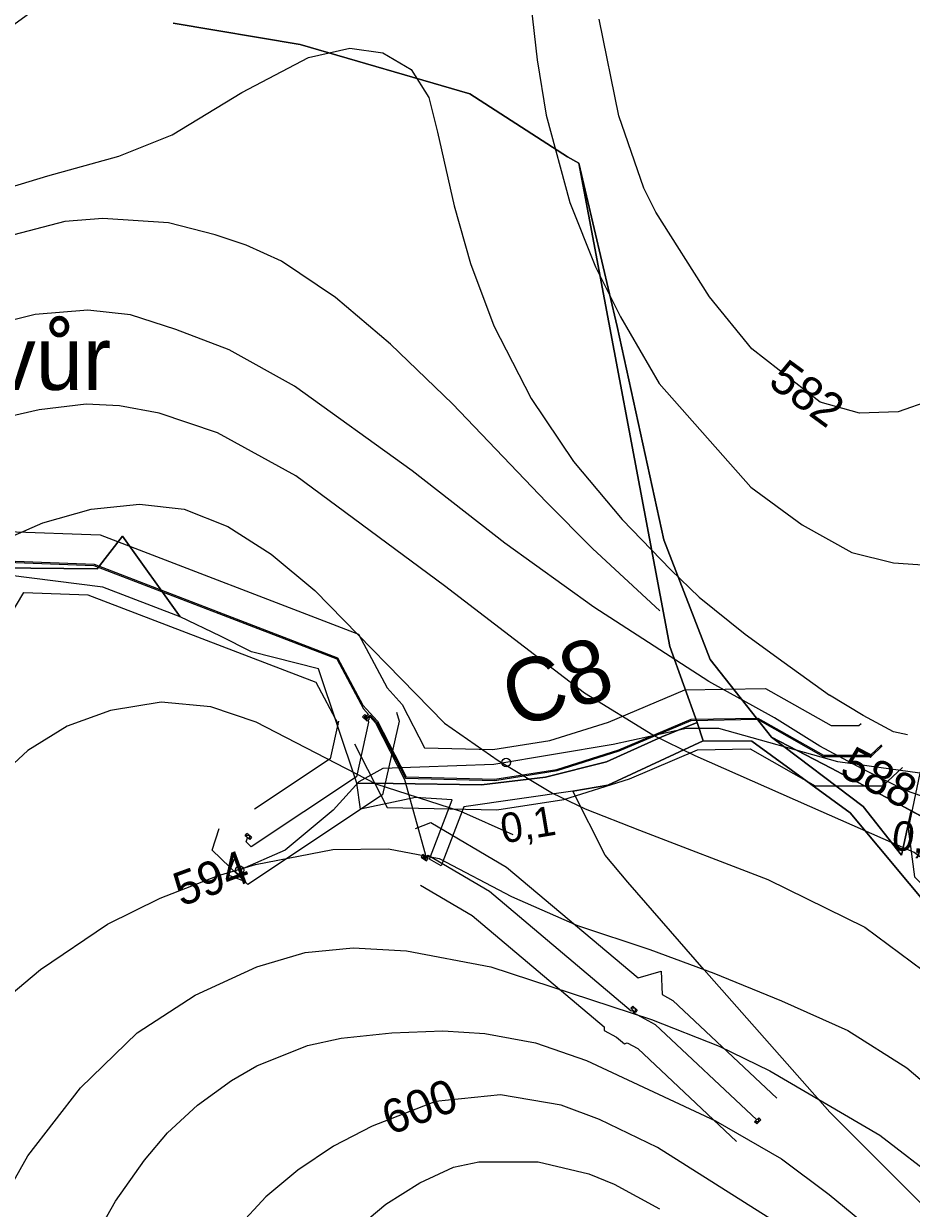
# Model space of a CAD drawing. Extents: x -709418 to -703832, y -1161719 to -1157826.
# Drawn here: x -705715.8 to -705505.5, y -1159483.1 to -1159202.3 of the extents above; entities that cross this region are included whole.
import ezdxf

# ---------------------------------------------------------------- set-up
doc = ezdxf.new("R2010")
doc.units = 0
for name, color, linetype in [('102_obvod PÚ', 7, 'Continuous'), ('103_hranice KÚ', 7, 'Continuous'), ('105_místní názvy', 7, 'Continuous'), ('110_silnice II. třídy a III. třídy', 7, 'Continuous'), ('120_vrstevnice hlavní', 7, 'Continuous'), ('121_vrstevnice hlavní_popis', 7, 'Continuous'), ('122_vrstevnice základní', 7, 'Continuous'), ('124_vrstevnice doplňková', 7, 'Continuous'), ('201_orná půda_KN', 7, 'Continuous'), ('206_TTP_KN', 7, 'Continuous'), ('210_ostatní plocha_KN', 7, 'Continuous'), ('301_polní cesta_stav', 7, 'Continuous'), ('302_polní cesta_stav_popis', 7, 'Continuous'), ('311_polní cesta_staničení', 7, 'Continuous'), ('708_el NN nadzemní a podzemní_ E.ON', 7, 'Continuous'), ('735_OP sítí TI', 7, 'Continuous'), ('Trasa-Hlavni  staniceni', 7, 'Continuous')]:
    doc.layers.add(name, color=color, linetype=linetype)

# ---------------------------------------------------------------- blocks, each defined once
blk = doc.blocks.new('Elektro - Implicitní$0$NN6301')
for points in [[(0, -0.7), (-0.7, 0)], [(-0.7, -0.7), (-0.7, 0), (0.7, 0), (0.7, -0.7)], [(-0.7, -0.7), (0.7, -0.7)], [(0, -0.7), (0.7, 0)]]:
    blk.add_lwpolyline(points)
blk = doc.blocks.new('Elektro - Implicitní$0$NN6201')
for points in [[(0.75, 0), (-0.75, 0)], [(-0.75, 0), (-0.75, -0.75)], [(0.75, -0.75), (0.75, 0)], [(-0.75, -0.75), (0.75, -0.75)], [(0.37, -0.18), (-0.38, -0.18)], [(-0.38, -0.18), (-0.38, -0.56)], [(-0.38, -0.56), (0.37, -0.56)], [(0.32, -0.23), (-0.33, -0.23)], [(-0.33, -0.23), (-0.33, -0.51)], [(-0.33, -0.51), (0.32, -0.51)], [(0.27, -0.27), (-0.28, -0.27)], [(-0.28, -0.27), (-0.28, -0.46)], [(-0.28, -0.46), (0.27, -0.46)], [(0.23, -0.32), (-0.23, -0.32)], [(-0.23, -0.32), (-0.23, -0.42)], [(-0.23, -0.42), (0.23, -0.42)], [(-0.19, -0.37), (0.19, -0.37)], [(0.23, -0.42), (0.23, -0.32)], [(0.27, -0.46), (0.27, -0.27)], [(0.32, -0.51), (0.32, -0.23)], [(0.37, -0.56), (0.37, -0.18)]]:
    blk.add_lwpolyline(points)
blk = doc.blocks.new('_kolecko-HB')
blk.add_circle((0, 0), 0.5)

msp = doc.modelspace()

# ---------------------------------------------------------------- linework, layer by layer
at = {"layer": '102_obvod PÚ'}
for points in [[(-705680.34, -1159202.12), (-705650.29, -1159207.21), (-705610.07, -1159218.91), (-705586.94, -1159233.79), (-705584.26, -1159235.35), (-705575.14, -1159274.02), (-705564.11, -1159324.58), (-705553.14, -1159353), (-705538.64, -1159371.35), (-705524.52, -1159378.74), (-705509.01, -1159386.99), (-705500.95, -1159391.28), (-705503.33, -1159398.39), (-705497.56, -1159411.85), (-705490.04, -1159416.53), (-705487.81, -1159418.64), (-705455.58, -1159447.44), (-705449.77, -1159447.44), (-705446.39, -1159448.44), (-705437.72, -1159450.61), (-705427.05, -1159453.12), (-705405.69, -1159458.61), (-705388.63, -1159462.82)], [(-705499.42, -1159485.62), (-705524.82, -1159460.29), (-705554.6, -1159426.55), (-705572.65, -1159405.79), (-705577.99, -1159399.35), (-705585.69, -1159384.22), (-705611.52, -1159387.9), (-705616.84, -1159401.92), (-705619.66, -1159400.28), (-705614.27, -1159386.22), (-705622.94, -1159385.65), (-705636, -1159388.43), (-705636.84, -1159382.26), (-705645.9, -1159355.21), (-705661.81, -1159351.18), (-705669.12, -1159347.43), (-705678.73, -1159342.87), (-705697, -1159335.87), (-705719.47, -1159333.02)]]:
    msp.add_lwpolyline(points, dxfattribs=at)
at = {"layer": '103_hranice KÚ'}
msp.add_lwpolyline([(-705225.01, -1159488.33), (-705244.62, -1159481.43), (-705265.81, -1159464.97), (-705344.08, -1159443.34), (-705385, -1159423.78), (-705409.33, -1159422.89), (-705434.44, -1159402.64), (-705455.51, -1159396.18), (-705483.68, -1159375.34), (-705500.95, -1159391.28), (-705509.01, -1159386.99), (-705524.52, -1159378.74), (-705538.64, -1159371.35), (-705553.14, -1159353), (-705564.11, -1159324.58), (-705575.14, -1159274.02), (-705584.26, -1159235.35), (-705586.94, -1159233.79), (-705610.07, -1159218.91), (-705650.29, -1159207.21), (-705680.34, -1159202.12)], dxfattribs=at)
at = {"layer": '110_silnice II. třídy a III. třídy'}
msp.add_lwpolyline([(-705425.72, -1159251.12), (-705459.29, -1159299.78), (-705480.06, -1159330.8), (-705495.83, -1159360.32), (-705503.49, -1159379.89), (-705506.27, -1159393.13), (-705504.73, -1159404.52), (-705453.28, -1159456.24), (-705424.63, -1159492.88), (-705411.38, -1159516.59), (-705404.7, -1159537.44), (-705401.75, -1159556.15), (-705377.61, -1159618.68), (-705336.72, -1159700.9), (-705321.44, -1159727.98), (-705286.96, -1159784.24)], dxfattribs=at)
at = {"layer": '120_vrstevnice hlavní'}
for points in [[(-705381.94, -1159487.18), (-705402.79, -1159477.04), (-705418.64, -1159469.88), (-705430.98, -1159461.82), (-705443.17, -1159452.24), (-705458.78, -1159437.51), (-705473.54, -1159423.6), (-705487.44, -1159411.53), (-705504.82, -1159398.74), (-705529.51, -1159387.8), (-705556.73, -1159375.81), (-705566.74, -1159370.95), (-705582.9, -1159360.93), (-705616.08, -1159335.48), (-705651.3, -1159309.45), (-705669.87, -1159299.28), (-705683.68, -1159294.6), (-705693.07, -1159292.84), (-705700.93, -1159292.46), (-705712.13, -1159293.77), (-705722.22, -1159296.11)], [(-705538.14, -1159486.07), (-705565.6, -1159468.62), (-705579.33, -1159462.05), (-705588.48, -1159458.61), (-705602.78, -1159456.18), (-705618.23, -1159457.75), (-705633.24, -1159463.62), (-705642.4, -1159468.34), (-705650.83, -1159474.06), (-705658.41, -1159480.35), (-705665.14, -1159487.64)]]:
    msp.add_lwpolyline(points, dxfattribs=at)
at = {"layer": '122_vrstevnice základní'}
for points in [[(-705719.49, -1159203.45), (-705705.95, -1159193.52), (-705691, -1159179.4), (-705675.18, -1159163.74), (-705664.19, -1159155.41), (-705651.93, -1159148.4), (-705644.22, -1159146.22), (-705636.86, -1159144.54), (-705629.16, -1159144.58), (-705621.63, -1159145.13), (-705613.95, -1159147.56), (-705607.81, -1159152.22), (-705602.38, -1159162.17), (-705599.36, -1159173.47), (-705595.59, -1159197.61), (-705594.12, -1159210.8), (-705591.96, -1159223.98), (-705586.39, -1159244.68), (-705580.31, -1159259.94), (-705574.38, -1159271.78), (-705565.22, -1159287.56), (-705543.49, -1159312.11), (-705531.39, -1159321.07), (-705519.61, -1159327.63)], [(-705443.75, -1159201.76), (-705457.62, -1159240.37), (-705466.63, -1159260.97), (-705477.36, -1159276.41), (-705484.94, -1159282.85), (-705496.38, -1159289.57), (-705500.96, -1159291.57), (-705508.63, -1159294.3), (-705517.78, -1159294.59), (-705527.05, -1159292), (-705543.31, -1159279.34), (-705553.3, -1159266.98), (-705566.03, -1159246.95), (-705568.89, -1159241.23), (-705574.75, -1159224.07), (-705579.47, -1159201.19)], [(-705727.83, -1159243.74), (-705710.02, -1159238.35), (-705693.24, -1159233.65), (-705680.56, -1159228.58), (-705664.1, -1159218.6), (-705648.28, -1159210.25), (-705638.52, -1159208.07), (-705630.66, -1159209.14), (-705624.01, -1159213.11), (-705619.77, -1159219.8), (-705617.76, -1159228.01), (-705613.81, -1159245.45), (-705609.95, -1159259.15), (-705604.38, -1159273.88), (-705595.55, -1159291.12), (-705585.53, -1159306.05), (-705573.97, -1159319.79), (-705562.45, -1159331.69), (-705555.73, -1159338.22), (-705544.84, -1159347), (-705535.63, -1159353.71), (-705524.9, -1159361.46)], [(-705537.93, -1159366.82), (-705553.44, -1159358.2), (-705580.67, -1159340.58), (-705601.79, -1159325.44), (-705623.75, -1159308.24), (-705651.58, -1159288.22), (-705667.09, -1159279.6), (-705679.71, -1159274.75), (-705690.46, -1159271.28), (-705700.54, -1159270.21), (-705713.05, -1159271.17), (-705729.82, -1159275.36)], [(-705725.35, -1159326.75), (-705711.19, -1159320.6), (-705699.75, -1159317.31), (-705688.3, -1159316.17), (-705677.72, -1159317.31), (-705667.43, -1159321.46), (-705657.13, -1159328.04), (-705646.83, -1159336.62), (-705616.08, -1159368.08), (-705603.35, -1159376.95), (-705590.48, -1159384.68), (-705582.76, -1159388.39), (-705569.89, -1159393.4), (-705539.46, -1159405.16), (-705516.52, -1159416.45), (-705502.65, -1159426.67), (-705489.28, -1159437.4), (-705477.39, -1159450.15), (-705458.29, -1159470.8), (-705430.41, -1159502.97)], [(-705519.61, -1159327.63), (-705509.7, -1159330.07), (-705501.67, -1159330.62), (-705492.59, -1159328.45), (-705484.41, -1159323.96)], [(-705506.41, -1159370.87), (-705509.72, -1159370.09), (-705516.89, -1159366.29), (-705524.9, -1159361.46)], [(-705506.91, -1159384.06), (-705517.14, -1159378.88), (-705527.2, -1159373.54), (-705537.93, -1159366.82)], [(-705300.15, -1159488.14), (-705312.94, -1159482.95), (-705322.66, -1159477.6), (-705336.8, -1159468.82), (-705349.59, -1159462.77), (-705374.26, -1159451.54), (-705386.37, -1159446.87), (-705397.11, -1159441.86), (-705410.13, -1159437.57), (-705423.1, -1159432.89), (-705431.62, -1159427.89), (-705443.03, -1159419.63), (-705453.75, -1159411.21), (-705478.41, -1159396.31), (-705497.35, -1159387.36), (-705506.91, -1159384.06)], [(-705719.2, -1159432.73), (-705711.76, -1159426.44), (-705695.88, -1159415.71), (-705683.44, -1159409.56), (-705669.86, -1159404.27), (-705660.85, -1159401.55), (-705642.54, -1159397.98), (-705629.38, -1159397.83), (-705617.37, -1159400.12), (-705600.21, -1159409.13), (-705584.56, -1159416.03), (-705567.41, -1159421.68), (-705552.26, -1159427.35), (-705536.27, -1159433.86), (-705520.53, -1159440.92), (-705506.52, -1159449.79), (-705496.03, -1159458.7), (-705482.37, -1159473.59), (-705460.54, -1159501.56)], [(-705731.49, -1159500.37), (-705714.76, -1159470.63), (-705702.32, -1159454.47), (-705688.88, -1159441.45), (-705675.15, -1159432.58), (-705660.56, -1159425.86), (-705649.12, -1159422.43), (-705637.68, -1159421.29), (-705625.09, -1159422), (-705605.07, -1159425.86), (-705567.03, -1159438.31), (-705551.01, -1159444.6), (-705539, -1159450.46), (-705512.97, -1159465.76), (-705498.81, -1159476.63), (-705489.23, -1159485.79), (-705480.08, -1159497.94), (-705465.92, -1159519.82), (-705457.34, -1159531.84), (-705440.6, -1159559.21), (-705429.51, -1159576.15), (-705417.92, -1159592.42), (-705402.43, -1159612.98)], [(-705704.61, -1159500.09), (-705694.03, -1159481.35), (-705687.16, -1159471.63), (-705681.73, -1159465.19), (-705674.58, -1159458.61), (-705666.57, -1159452.75), (-705660.56, -1159449.32), (-705648.55, -1159444.45), (-705640.54, -1159442.74), (-705628.53, -1159441.45), (-705616.51, -1159441.02), (-705606.5, -1159441.59), (-705594.49, -1159443.88), (-705582.47, -1159448.03), (-705551.87, -1159462.33), (-705536.28, -1159471.34), (-705524.98, -1159479.78), (-705506.82, -1159494.8)], [(-705637.39, -1159488.36), (-705629.96, -1159482.07), (-705621.95, -1159477.06), (-705613.94, -1159473.34), (-705607.93, -1159472.06), (-705593.92, -1159472.06), (-705581.9, -1159474.92), (-705575.9, -1159477.35), (-705565.17, -1159483.21)]]:
    msp.add_lwpolyline(points, dxfattribs=at)
at = {"layer": '124_vrstevnice doplňková'}
for points in [[(-705565.05, -1159341.43), (-705581.05, -1159326.64), (-705591.93, -1159315.65), (-705614.21, -1159292.34), (-705628.84, -1159278.25), (-705641.9, -1159267.15), (-705654.68, -1159258.53), (-705663.04, -1159254.73), (-705670.38, -1159252.3), (-705681.48, -1159249.51), (-705696.98, -1159248.48), (-705706.04, -1159249.12), (-705719.91, -1159252.81)], [(-705599.78, -1159394.54), (-705612.22, -1159388.97), (-705632.24, -1159382.53), (-705660.7, -1159367.8), (-705671.43, -1159364.22), (-705683.16, -1159363.08), (-705695.17, -1159365.08), (-705705.47, -1159368.8), (-705714.76, -1159374.52), (-705724.77, -1159383.82), (-705732.07, -1159393.26), (-705738.93, -1159403.7), (-705749.37, -1159422.57), (-705762.1, -1159452.89), (-705769.54, -1159468.05), (-705776.97, -1159481.35)]]:
    msp.add_lwpolyline(points, dxfattribs=at)
at = {"layer": '201_orná půda_KN'}
for p, q in [((-705577.37, -1159382.76), (-705554.77, -1159372.22)), ((-705554.77, -1159372.22), (-705543.28, -1159372.33)), ((-705543.28, -1159372.33), (-705519.98, -1159389.35)), ((-705585.69, -1159384.22), (-705577.37, -1159382.76)), ((-705577.99, -1159399.35), (-705585.69, -1159384.22)), ((-705519.98, -1159389.35), (-705494.61, -1159419.82)), ((-705572.65, -1159405.79), (-705577.99, -1159399.35)), ((-705554.6, -1159426.55), (-705572.65, -1159405.79)), ((-705524.82, -1159460.29), (-705554.6, -1159426.55)), ((-705499.42, -1159485.62), (-705524.82, -1159460.29))]:
    msp.add_line(p, q, dxfattribs=at)
at = {"layer": '206_TTP_KN'}
for p, q in [((-705680.34, -1159202.12), (-705650.29, -1159207.21)), ((-705650.29, -1159207.21), (-705610.07, -1159218.91)), ((-705610.07, -1159218.91), (-705586.94, -1159233.79)), ((-705586.94, -1159233.79), (-705584.26, -1159235.35)), ((-705584.26, -1159235.35), (-705562.73, -1159349.9)), ((-705692.37, -1159323.71), (-705698.36, -1159331.52)), ((-705678.73, -1159342.87), (-705692.37, -1159323.71)), ((-705698.36, -1159331.52), (-705750.92, -1159330.91)), ((-705669.12, -1159347.43), (-705678.73, -1159342.87)), ((-705661.81, -1159351.18), (-705669.12, -1159347.43)), ((-705562.73, -1159349.9), (-705556.21, -1159367.9)), ((-705645.9, -1159355.21), (-705661.81, -1159351.18)), ((-705636.84, -1159382.26), (-705645.9, -1159355.21)), ((-705556.21, -1159367.9), (-705564.61, -1159371.29)), ((-705564.61, -1159371.29), (-705577.74, -1159377.22)), ((-705577.74, -1159377.22), (-705592.15, -1159380.86)), ((-705592.15, -1159380.86), (-705607.28, -1159382.71)), ((-705628.24, -1159382.39), (-705636.84, -1159382.26)), ((-705607.28, -1159382.71), (-705628.24, -1159382.39))]:
    msp.add_line(p, q, dxfattribs=at)
at = {"layer": '210_ostatní plocha_KN'}
for p, q in [((-705584.26, -1159235.35), (-705575.14, -1159274.02)), ((-705562.73, -1159349.9), (-705584.26, -1159235.35)), ((-705575.14, -1159274.02), (-705564.11, -1159324.58)), ((-705698.36, -1159331.52), (-705692.37, -1159323.71)), ((-705692.37, -1159323.71), (-705678.73, -1159342.87)), ((-705564.11, -1159324.58), (-705553.14, -1159353)), ((-705750.92, -1159330.91), (-705698.36, -1159331.52)), ((-705697, -1159335.87), (-705719.47, -1159333.02)), ((-705678.73, -1159342.87), (-705697, -1159335.87)), ((-705556.21, -1159367.9), (-705562.73, -1159349.9)), ((-705553.14, -1159353), (-705538.64, -1159371.35)), ((-705564.61, -1159371.29), (-705556.21, -1159367.9)), ((-705554.77, -1159372.22), (-705556.21, -1159367.9)), ((-705556.21, -1159367.9), (-705554.77, -1159372.22)), ((-705577.74, -1159377.22), (-705564.61, -1159371.29)), ((-705554.77, -1159372.22), (-705577.37, -1159382.76)), ((-705543.28, -1159372.33), (-705554.77, -1159372.22)), ((-705519.98, -1159389.35), (-705543.28, -1159372.33)), ((-705538.64, -1159371.35), (-705516.91, -1159387.84)), ((-705538.64, -1159371.35), (-705524.52, -1159378.74)), ((-705516.91, -1159387.84), (-705538.64, -1159371.35)), ((-705592.15, -1159380.86), (-705577.74, -1159377.22)), ((-705607.28, -1159382.71), (-705592.15, -1159380.86)), ((-705524.52, -1159378.74), (-705509.01, -1159386.99)), ((-705636.84, -1159382.26), (-705628.24, -1159382.39)), ((-705636, -1159388.43), (-705636.84, -1159382.26)), ((-705628.24, -1159382.39), (-705607.28, -1159382.71)), ((-705577.37, -1159382.76), (-705585.69, -1159384.22)), ((-705622.94, -1159385.65), (-705636, -1159388.43)), ((-705614.27, -1159386.22), (-705622.94, -1159385.65)), ((-705619.66, -1159400.28), (-705614.27, -1159386.22)), ((-705585.69, -1159384.22), (-705611.52, -1159387.9)), ((-705611.52, -1159387.9), (-705616.84, -1159401.92)), ((-705494.61, -1159419.82), (-705519.98, -1159389.35)), ((-705516.91, -1159387.84), (-705507.85, -1159399.33)), ((-705507.85, -1159399.33), (-705516.91, -1159387.84)), ((-705509.01, -1159386.99), (-705505.51, -1159388.85)), ((-705507.85, -1159399.33), (-705505.51, -1159388.85)), ((-705505.51, -1159388.85), (-705507.85, -1159399.33)), ((-705505.51, -1159388.85), (-705500.95, -1159391.28)), ((-705616.84, -1159401.92), (-705619.66, -1159400.28))]:
    msp.add_line(p, q, dxfattribs=at)
at = {"layer": '301_polní cesta_stav'}
msp.add_lwpolyline([(-705503.49, -1159379.89), (-705522.89, -1159377.26), (-705551.11, -1159369.34), (-705558.72, -1159369.34), (-705576.15, -1159373.14), (-705604.37, -1159377.89), (-705630.69, -1159378.84), (-705636.39, -1159382.01), (-705642.42, -1159388.66), (-705653.83, -1159398.17), (-705664.6, -1159402.88)], dxfattribs=at)
at = {"layer": '311_polní cesta_staničení'}
msp.add_lwpolyline([(-705663.37, -1159405.62), (-705667.34, -1159404.11), (-705665.83, -1159400.14), (-705663.37, -1159405.62)], dxfattribs=at)
at = {"layer": '708_el NN nadzemní a podzemní_ E.ON'}
for points in [[(-705855.93, -1159401.12), (-705855.92, -1159400.72), (-705847.08, -1159396.96), (-705827.18, -1159390.88), (-705803.33, -1159354.74), (-705793.77, -1159342.85), (-705763.01, -1159338.71), (-705751.89, -1159329.66), (-705720.23, -1159329.92), (-705719.92, -1159330.33), (-705719.68, -1159329.92), (-705699.16, -1159330.7), (-705641.6, -1159352.79), (-705635.28, -1159364.66), (-705634.08, -1159366.04), (-705634.52, -1159366.43)], [(-705719.85, -1159329.61), (-705699.1, -1159330.4), (-705641.39, -1159352.55), (-705635.41, -1159363.78), (-705631.93, -1159367.63), (-705625.16, -1159380.82), (-705604.17, -1159381.34), (-705589.48, -1159379.02), (-705574.78, -1159374.38), (-705557.68, -1159367.12), (-705541.82, -1159366.86), (-705526.32, -1159375.65), (-705515.14, -1159375.65), (-705512.54, -1159373.19)], [(-705851.28, -1159406.35), (-705844.68, -1159403.55), (-705822.73, -1159396.84), (-705797.67, -1159358.87), (-705790.07, -1159349.41), (-705760.12, -1159345.38), (-705749.43, -1159336.68), (-705723.73, -1159336.89), (-705719.18, -1159342.92), (-705715.76, -1159337.07), (-705700.59, -1159337.65), (-705646.55, -1159358.39), (-705641.25, -1159368.33)], [(-705634.32, -1159366.65), (-705633.67, -1159366.15), (-705632.18, -1159367.8), (-705625.34, -1159381.12), (-705604.15, -1159381.64), (-705589.41, -1159379.31), (-705574.68, -1159374.66), (-705557.62, -1159367.42), (-705541.9, -1159367.16), (-705526.4, -1159375.95), (-705515.02, -1159375.95), (-705512.4, -1159373.46)], [(-705634.09, -1159366.86), (-705633.71, -1159366.56), (-705632.43, -1159367.97), (-705625.52, -1159381.42), (-705620.63, -1159399.04), (-705620.59, -1159399.49)], [(-705634.18, -1159367.37), (-705634.05, -1159367.83), (-705636.96, -1159380.76), (-705661.86, -1159397.36), (-705663.08, -1159396.17), (-705662.77, -1159395.22)], [(-705620.48, -1159399.56), (-705619.98, -1159399.37), (-705605.44, -1159407.9), (-705571.84, -1159436.27), (-705571.41, -1159436.14), (-705571.39, -1159436.66), (-705566.15, -1159439.5), (-705542.13, -1159462.09)]]:
    msp.add_lwpolyline(points, dxfattribs=at)
at = {"layer": '735_OP sítí TI'}
for points in [[(-705719.69, -1159322.61), (-705697.67, -1159323.45), (-705636.44, -1159346.95), (-705629.64, -1159359.73), (-705626.12, -1159363.62), (-705620.83, -1159373.93), (-705604.63, -1159374.33), (-705591.09, -1159372.18), (-705577.21, -1159367.8), (-705559.16, -1159360.14), (-705540.03, -1159359.83), (-705524.47, -1159368.65), (-705517.93, -1159368.65), (-705517.36, -1159368.11)], [(-705627.45, -1159365.45), (-705626.83, -1159367.62), (-705630.75, -1159385.03), (-705662.69, -1159406.33), (-705671.09, -1159398.14), (-705669.42, -1159393.05)], [(-705641.18, -1159367.62), (-705643.17, -1159376.49), (-705661.08, -1159388.43)], [(-705637.41, -1159372.93), (-705629.67, -1159388.02), (-705603.69, -1159388.65), (-705587.8, -1159386.14), (-705572.25, -1159381.23), (-705556.14, -1159374.4), (-705543.69, -1159374.19), (-705528.25, -1159382.95), (-705512.23, -1159382.95), (-705507.58, -1159378.54)], [(-705622.97, -1159393.02), (-705619.33, -1159391.64), (-705601.38, -1159402.17), (-705570.23, -1159428.47), (-705564.76, -1159426.82), (-705564.55, -1159432.41), (-705562.02, -1159433.78), (-705537.33, -1159456.99)], [(-705621.76, -1159406.44), (-705609.5, -1159413.63), (-705578.27, -1159440.01), (-705578.23, -1159440.91), (-705575.32, -1159442.49), (-705573.45, -1159444.07), (-705572.78, -1159443.87), (-705570.28, -1159445.22), (-705546.93, -1159467.19)]]:
    msp.add_lwpolyline(points, dxfattribs=at)

# ---------------------------------------------------------------- block references
at = {"layer": '708_el NN nadzemní a podzemní_ E.ON'}
for name, p, rotation in [('Elektro - Implicitní$0$NN6201', (-705634.42, -1159366.54), -44.093830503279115), ('Elektro - Implicitní$0$NN6301', (-705662.77, -1159395.22), 142.70064998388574), ('Elektro - Implicitní$0$NN6201', (-705620.59, -1159399.64), -32.597122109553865), ('Elektro - Implicitní$0$NN6301', (-705571.41, -1159436.14), 136.00013607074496), ('Elektro - Implicitní$0$NN6301', (-705542.13, -1159462.09), 46.567577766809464)]:
    msp.add_blockref(name, p, dxfattribs=dict(at, rotation=rotation))
at = {"layer": 'Trasa-Hlavni  staniceni', "xscale": 1.999999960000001}
for p, yscale, rotation in [((-705601.46, -1159377.4), 1.9999999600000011, -170.43916835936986), ((-705664.6, -1159402.88), 1.9999999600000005, -156.3837709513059)]:
    msp.add_blockref('_kolecko-HB', p, dxfattribs=dict(at, yscale=yscale, rotation=rotation))

# ---------------------------------------------------------------- texts
at = {"layer": '105_místní názvy'}
msp.add_text('Kunějovský Dvůr', height=15, dxfattribs=at).set_placement((-705845.56, -1159289.08))
at = {"layer": '121_vrstevnice hlavní_popis'}
for s, rotation, p in [('582', 323.7777, (-705539.72, -1159287.83)), ('588', 332.2369, (-705522.87, -1159380.32)), ('594', 20.0285, (-705678.44, -1159411.59)), ('600', 20.4219, (-705628.99, -1159465.79))]:
    msp.add_text(s, height=8, rotation=rotation, dxfattribs=at).set_placement(p)
at = {"layer": '302_polní cesta_stav_popis'}
msp.add_text('C8', height=15, rotation=18.4242, dxfattribs=at).set_placement((-705599.29, -1159369.43))
at = {"layer": 'Trasa-Hlavni  staniceni'}
for s, height, rotation, p in [('0,1', 7, 9.5608, (-705602.16, -1159396.61)), ('0,0', 7, 352.2674, (-705510.4, -1159397.95)), ('0,2', 0.000000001, 23.6162, (-705657.28, -1159417.14))]:
    msp.add_text(s, height=height, rotation=rotation, dxfattribs=at).set_placement(p)

doc.saveas('drawing.dxf')
